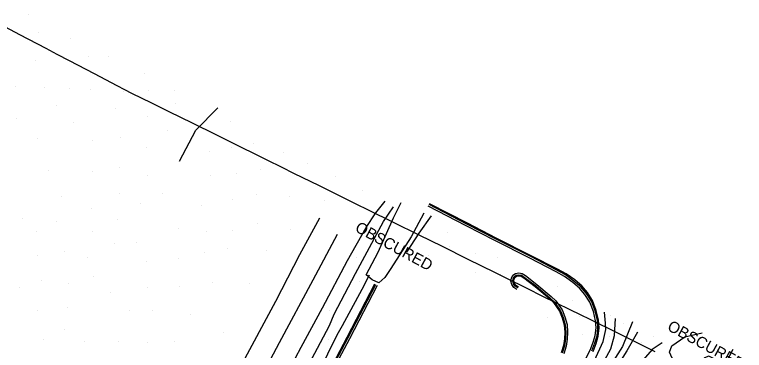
# Model space of a CAD drawing. Extents: x 1497074 to 1501343, y 481943 to 486114.
# Drawn here: x 1498306.3 to 1498696.9, y 483689.7 to 483869.7 of the extents above; entities that cross this region are included whole.
import ezdxf

# ---------------------------------------------------------------- set-up
doc = ezdxf.new("R2010")
doc.units = 0
for name, color, linetype in [('PH Exist DTM Boundary', 7, 'Continuous'), ('PH Exist DTM Breakline', 7, 'Continuous'), ('PH Exist DTM Obscure Area', 7, 'Continuous'), ('PH Exist DTM Obscure Area Text', 7, 'Continuous'), ('PH Exist DTM Point', 7, 'Continuous')]:
    doc.layers.add(name, color=color, linetype=linetype)

msp = doc.modelspace()

# ---------------------------------------------------------------- linework, layer by layer
at = {"layer": 'PH Exist DTM Boundary'}
msp.add_lwpolyline([(1498649.09, 483689.06), (1498644.16, 483691.49), (1498629.09, 483698.94), (1498614.35, 483706.23), (1498609.09, 483708.83), (1498603.71, 483711.49), (1498589.09, 483718.72), (1498580.54, 483722.94), (1498569.09, 483728.6), (1498563.25, 483731.49), (1498549.09, 483738.49), (1498535.25, 483745.34), (1498529.09, 483748.38), (1498522.79, 483751.49), (1498509.09, 483758.27), (1498495.69, 483764.89), (1498489.09, 483768.15), (1498482.34, 483771.49), (1498469.09, 483778.04), (1498456.14, 483784.44), (1498449.09, 483787.93), (1498441.88, 483791.49), (1498433.32, 483795.72), (1498429.09, 483797.81), (1498419.94, 483802.34), (1498409.09, 483807.7), (1498406.55, 483808.95), (1498401.42, 483811.49), (1498389.09, 483817.59), (1498379.79, 483822.19), (1498369.09, 483827.48), (1498365.25, 483829.38), (1498365.25, 483829.38), (1498361.22, 483831.49), (1498349.09, 483837.86), (1498335.68, 483844.9), (1498329.09, 483848.36), (1498323.13, 483851.49), (1498309.09, 483858.86), (1498293.57, 483867.02)], dxfattribs=at)
at = {"layer": 'PH Exist DTM Breakline'}
for points in [[(1498394.59, 483791.1), (1498403.33, 483807.83), (1498415.01, 483819.74)], [(1498447.55, 483668.63), (1498459.74, 483691.55), (1498471.13, 483712.57), (1498484.43, 483737.88), (1498494.44, 483755.53), (1498499.66, 483763.4), (1498504.61, 483769.78)], [(1498447.31, 483651.62), (1498456.12, 483667.84), (1498468.39, 483691), (1498474.9, 483703.04), (1498477.38, 483709.2), (1498488.75, 483730.88), (1498499.95, 483751.82), (1498503.73, 483758.77), (1498509.04, 483766.64)], [(1498609.26, 483680.32), (1498614.34, 483689.93), (1498615.96, 483694.09), (1498617.03, 483697.81), (1498617.51, 483701.92), (1498617.22, 483705.66), (1498616.12, 483710.64), (1498614.2, 483715.63), (1498611.52, 483719.72), (1498608.69, 483723.03), (1498605, 483726.12), (1498600.56, 483729.4), (1498596.06, 483731.92), (1498582.06, 483739.09), (1498563.27, 483748.6), (1498547.95, 483756.53), (1498527.67, 483767.02)], [(1498615.25, 483689.51), (1498616.91, 483693.77), (1498618.02, 483697.61), (1498618.52, 483701.9), (1498618.21, 483705.81), (1498617.08, 483710.93), (1498615.1, 483716.09), (1498612.32, 483720.32), (1498609.4, 483723.74), (1498605.62, 483726.91), (1498601.1, 483730.24), (1498596.54, 483732.8), (1498582.51, 483739.98), (1498563.73, 483749.49), (1498548.41, 483757.42), (1498528.13, 483767.91)], [(1498615.9, 483689.2), (1498617.58, 483693.5), (1498618.62, 483697.45), (1498619.13, 483701.83), (1498618.85, 483706.16), (1498617.62, 483711.19), (1498615.61, 483716.44), (1498612.96, 483720.71), (1498609.88, 483724.34), (1498606.08, 483727.58), (1498601.42, 483730.76), (1498596.77, 483733.24), (1498582.74, 483740.42), (1498563.96, 483749.93), (1498548.64, 483757.86), (1498528.36, 483768.35)], [(1498516.2, 483742.31), (1498522.77, 483752.51), (1498529.37, 483761.85)], [(1498469.5, 483760.69), (1498458.69, 483740.87), (1498445.85, 483715.88), (1498427.04, 483680.74), (1498412.85, 483653.78), (1498398.64, 483627.6), (1498382.78, 483598.45), (1498367.78, 483569.73), (1498363.44, 483561.65), (1498358.69, 483552.93), (1498349.41, 483535.78)], [(1498478.85, 483751.89), (1498465.83, 483727.47), (1498447.89, 483693.89), (1498430.39, 483660.8), (1498410.39, 483624.69), (1498396.32, 483598.79), (1498378.24, 483563.99), (1498373.07, 483554.34), (1498364.15, 483537.79)], [(1498462.83, 483653.45), (1498463.68, 483662.71), (1498467.39, 483674.3), (1498473.87, 483687.85), (1498477.52, 483695.25), (1498479.71, 483699.27), (1498481.74, 483703.02), (1498492.34, 483722.64), (1498496.18, 483730.2)], [(1498575.09, 483722.38), (1498573.54, 483723.47), (1498572.39, 483725.01), (1498571.87, 483726.78), (1498572.2, 483728.54), (1498572.98, 483729.98), (1498574.4, 483731), (1498576.13, 483731.28), (1498577.9, 483730.92), (1498579.67, 483729.8), (1498585.85, 483725.08), (1498593.5, 483718.71), (1498595.89, 483716.33), (1498599.3, 483711.51), (1498600.86, 483707.73), (1498601.99, 483703.69), (1498602.25, 483699.57), (1498602.05, 483695.78), (1498601.52, 483692.07), (1498600.31, 483687.96)], [(1498575.67, 483723.19), (1498574.25, 483724.2), (1498573.3, 483725.47), (1498572.9, 483726.83), (1498573.15, 483728.2), (1498573.75, 483729.3), (1498574.8, 483730.05), (1498576.11, 483730.27), (1498577.53, 483729.98), (1498579.1, 483728.98), (1498585.23, 483724.3), (1498592.83, 483717.97), (1498595.13, 483715.69), (1498598.42, 483711.02), (1498599.91, 483707.4), (1498600.99, 483703.52), (1498601.25, 483699.57), (1498601.05, 483695.88), (1498600.54, 483692.28), (1498599.37, 483688.31)], [(1498575.96, 483723.6), (1498574.6, 483724.56), (1498573.76, 483725.69), (1498573.41, 483726.86), (1498573.63, 483728.03), (1498574.13, 483728.96), (1498574.99, 483729.58), (1498576.1, 483729.76), (1498577.34, 483729.51), (1498578.81, 483728.57), (1498584.92, 483723.91), (1498592.49, 483717.6), (1498594.74, 483715.36), (1498597.98, 483710.78), (1498599.44, 483707.24), (1498600.5, 483703.43), (1498600.75, 483699.56), (1498600.55, 483695.93), (1498600.05, 483692.39), (1498598.9, 483688.48)], [(1498499, 483725.16), (1498484.14, 483696.71), (1498472.63, 483674.8), (1498469.77, 483668.91), (1498468.56, 483665.61), (1498468.16, 483661.61), (1498468.3, 483656.92), (1498469.19, 483651.15), (1498469.88, 483647.53), (1498470.59, 483644.55), (1498471.25, 483641.04), (1498471.75, 483638.62), (1498471.77, 483637.44), (1498471.41, 483636.54), (1498470.81, 483635.6), (1498470, 483634.96), (1498468.72, 483634.39), (1498458.46, 483630.94), (1498446.44, 483627.08), (1498434.98, 483604.76), (1498418.09, 483571.55), (1498405.83, 483547.74), (1498402.54, 483541.58)], [(1498499.44, 483724.93), (1498484.58, 483696.48), (1498473.08, 483674.58), (1498470.23, 483668.72), (1498469.05, 483665.5), (1498468.66, 483661.6), (1498468.8, 483656.96), (1498469.68, 483651.24), (1498470.37, 483647.64), (1498471.44, 483643.34), (1498471.87, 483640.8), (1498472.24, 483638.66), (1498472.27, 483637.35), (1498471.86, 483636.31), (1498471.19, 483635.26), (1498470.25, 483634.53), (1498468.9, 483633.93), (1498458.61, 483630.46), (1498446.79, 483626.67), (1498435.43, 483604.53), (1498418.53, 483571.32), (1498406.28, 483547.51), (1498402.99, 483541.34)], [(1498500.33, 483724.47), (1498485.47, 483696.01), (1498473.97, 483674.13), (1498471.15, 483668.33), (1498470.03, 483665.28), (1498469.66, 483661.56), (1498469.8, 483657.06), (1498470.67, 483651.41), (1498471.35, 483647.85), (1498472.42, 483643.55), (1498472.86, 483640.97), (1498473.24, 483638.76), (1498473.27, 483637.17), (1498472.76, 483635.85), (1498471.94, 483634.58), (1498470.77, 483633.67), (1498469.27, 483633), (1498458.93, 483629.51), (1498447.49, 483625.84), (1498436.32, 483604.08), (1498419.42, 483570.87), (1498407.16, 483547.04), (1498403.87, 483540.87)], [(1498607.62, 483660.62), (1498618.73, 483678.45), (1498625.37, 483690.67), (1498627.28, 483697.77), (1498627.89, 483706.87)], [(1498616.68, 483684.38), (1498621.23, 483694.54), (1498622.65, 483700.97), (1498622.59, 483704.26), (1498621.96, 483710.17)], [(1498637.05, 483704.99), (1498631.7, 483691.92), (1498619.12, 483672.24), (1498611, 483658.42), (1498607.04, 483651.85), (1498605.3, 483649.51)], [(1498639.72, 483699.61), (1498633.95, 483689.47), (1498626.48, 483677.64), (1498618.91, 483663.71), (1498612.15, 483651.28), (1498606.53, 483640.29)], [(1498652.87, 483693.82), (1498647.54, 483690.22), (1498642.72, 483684.67), (1498640.91, 483681.33), (1498632.44, 483665.76), (1498627.85, 483659.13), (1498625.92, 483656.1), (1498619.06, 483647.67), (1498617, 483644.56), (1498610.31, 483632.71), (1498602.41, 483618.88), (1498592.1, 483600.32), (1498583.97, 483584.33), (1498573.56, 483565.19), (1498565.32, 483546.58), (1498558.67, 483532.03), (1498554.72, 483524.73), (1498547.04, 483510.4), (1498540.16, 483495.31), (1498533.88, 483484.36), (1498530.79, 483479.09)]]:
    msp.add_lwpolyline(points, dxfattribs=at)
at = {"layer": 'PH Exist DTM Obscure Area'}
for points in [[(1498525.32, 483763.24), (1498518.48, 483750.67), (1498507.61, 483733.58), (1498504.39, 483728.88), (1498501.31, 483725.91), (1498497.66, 483727.52), (1498494.54, 483730.29), (1498500.85, 483742.33), (1498509.14, 483760.81), (1498513.11, 483768.91)], [(1498690.72, 483690.16), (1498686.86, 483683.07), (1498685.66, 483682.7), (1498677.93, 483686.67), (1498675.62, 483685.75), (1498672.91, 483680.83), (1498669.44, 483679.83), (1498662.45, 483682.75), (1498658.15, 483685.66), (1498656.82, 483688.74), (1498658.12, 483692.11), (1498665.06, 483697.03), (1498674.36, 483699.13)]]:
    msp.add_lwpolyline(points, dxfattribs=at)
at = {"layer": 'PH Exist DTM Point'}
for p, q in [((1498313.78, 483869.68), (1498313.78, 483869.68)), ((1498318.86, 483860.12), (1498318.86, 483860.12)), ((1498336.05, 483856.99), (1498336.05, 483856.99)), ((1498317.66, 483844.97), (1498317.66, 483844.97)), ((1498345.63, 483847.18), (1498345.63, 483847.18)), ((1498356.69, 483847), (1498356.69, 483847)), ((1498375.94, 483838.05), (1498375.94, 483838.05)), ((1498306.62, 483831.17), (1498306.62, 483831.17)), ((1498322.43, 483830.39), (1498322.43, 483830.39)), ((1498335.44, 483830.01), (1498335.44, 483830.01)), ((1498347.12, 483829.4), (1498347.12, 483829.4)), ((1498364.39, 483828.46), (1498364.39, 483828.46)), ((1498377.83, 483828.85), (1498377.83, 483828.85)), ((1498392.11, 483828.8), (1498392.11, 483828.8)), ((1498328.92, 483820.75), (1498328.92, 483820.75)), ((1498392.18, 483821.78), (1498392.18, 483821.78)), ((1498360.5, 483819.3), (1498360.5, 483819.3)), ((1498415.01, 483819.74), (1498415.01, 483819.74)), ((1498307.37, 483814.15), (1498307.37, 483814.15)), ((1498377.55, 483815.19), (1498377.55, 483815.19)), ((1498421.82, 483812.51), (1498421.82, 483812.51)), ((1498337.81, 483811.73), (1498337.81, 483811.73)), ((1498387.95, 483807.68), (1498387.95, 483807.68)), ((1498403.33, 483807.83), (1498403.33, 483807.83)), ((1498318.63, 483803.18), (1498318.63, 483803.18)), ((1498347.86, 483802.47), (1498347.86, 483802.47)), ((1498362.77, 483803.79), (1498362.77, 483803.79)), ((1498434.33, 483800.76), (1498434.33, 483800.76)), ((1498376.66, 483798.22), (1498376.66, 483798.22)), ((1498422.48, 483798.5), (1498422.48, 483798.5)), ((1498410.72, 483796.25), (1498410.72, 483796.25)), ((1498450.18, 483795.67), (1498450.18, 483795.67)), ((1498394.59, 483791.1), (1498394.59, 483791.1)), ((1498463.09, 483789.89), (1498463.09, 483789.89)), ((1498324.51, 483786.04), (1498324.51, 483786.04)), ((1498348.21, 483785.8), (1498348.21, 483785.8)), ((1498362.41, 483787.93), (1498362.41, 483787.93)), ((1498425.19, 483784.75), (1498425.19, 483784.75)), ((1498437.67, 483786.42), (1498437.67, 483786.42)), ((1498377.52, 483783.21), (1498377.52, 483783.21)), ((1498410.9, 483783.4), (1498410.9, 483783.4)), ((1498478.03, 483782.73), (1498478.03, 483782.73)), ((1498362.52, 483773.78), (1498362.52, 483773.78)), ((1498385.51, 483773.73), (1498385.51, 483773.73)), ((1498436.01, 483773.32), (1498436.01, 483773.32)), ((1498492.55, 483775.36), (1498492.55, 483775.36)), ((1498331.46, 483772.18), (1498331.46, 483772.18)), ((1498422.97, 483770.8), (1498422.97, 483770.8)), ((1498453.51, 483772.26), (1498453.51, 483772.26)), ((1498472.03, 483770.27), (1498472.03, 483770.27)), ((1498347.63, 483765.56), (1498347.63, 483765.56)), ((1498373.85, 483768.48), (1498373.85, 483768.48)), ((1498406.55, 483767.64), (1498406.55, 483767.64)), ((1498310.66, 483760.18), (1498310.66, 483760.18)), ((1498328.47, 483758.79), (1498328.47, 483758.79)), ((1498361.6, 483759.99), (1498361.6, 483759.99)), ((1498436.06, 483757.8), (1498436.06, 483757.8)), ((1498318.13, 483753.61), (1498318.13, 483753.61)), ((1498348.04, 483753.5), (1498348.04, 483753.5)), ((1498393.99, 483754.84), (1498393.99, 483754.84)), ((1498408.9, 483753.59), (1498408.9, 483753.59)), ((1498422.74, 483753.91), (1498422.74, 483753.91)), ((1498454.17, 483754.34), (1498454.17, 483754.34)), ((1498537.87, 483752.81), (1498537.87, 483752.81)), ((1498359.84, 483746.96), (1498359.84, 483746.96)), ((1498371.54, 483747.44), (1498371.54, 483747.44)), ((1498332.85, 483742.69), (1498332.85, 483742.69)), ((1498407.89, 483742.24), (1498407.89, 483742.24)), ((1498420.14, 483744.11), (1498420.14, 483744.11)), ((1498441.23, 483743.48), (1498441.23, 483743.48)), ((1498538.94, 483745.43), (1498538.94, 483745.43)), ((1498318.31, 483740.36), (1498318.31, 483740.36)), ((1498345.42, 483739.46), (1498345.42, 483739.46)), ((1498393.88, 483738.85), (1498393.88, 483738.85)), ((1498489.44, 483739.37), (1498489.44, 483739.37)), ((1498527.63, 483740.84), (1498527.63, 483740.84)), ((1498553.11, 483741.58), (1498553.11, 483741.58)), ((1498564.71, 483739.48), (1498564.71, 483739.48)), ((1498377.08, 483737.26), (1498377.08, 483737.26)), ((1498552.71, 483731.58), (1498552.71, 483731.58)), ((1498566.3, 483730.42), (1498566.3, 483730.42)), ((1498320.72, 483727.46), (1498320.72, 483727.46)), ((1498348.44, 483729.45), (1498348.44, 483729.45)), ((1498490.8, 483726.79), (1498490.8, 483726.79)), ((1498308.96, 483723.46), (1498308.96, 483723.46)), ((1498334.96, 483725.6), (1498334.96, 483725.6)), ((1498377.4, 483723.33), (1498377.4, 483723.33)), ((1498394.34, 483723.99), (1498394.34, 483723.99)), ((1498412.38, 483726.1), (1498412.38, 483726.1)), ((1498432.27, 483725.61), (1498432.27, 483725.61)), ((1498597.12, 483724.03), (1498597.12, 483724.03)), ((1498357.79, 483720.88), (1498357.79, 483720.88)), ((1498604.75, 483716.49), (1498604.75, 483716.49)), ((1498318.65, 483710.96), (1498318.65, 483710.96)), ((1498334.39, 483712.83), (1498334.39, 483712.83)), ((1498367.8, 483711.03), (1498367.8, 483711.03)), ((1498380.27, 483711.31), (1498380.27, 483711.31)), ((1498474.72, 483711.22), (1498474.72, 483711.22)), ((1498400.56, 483708.99), (1498400.56, 483708.99)), ((1498591.72, 483707.23), (1498591.72, 483707.23)), ((1498608.69, 483707.94), (1498608.69, 483707.94)), ((1498625.21, 483708.59), (1498625.21, 483708.59)), ((1498632.07, 483704.13), (1498632.07, 483704.13)), ((1498333.22, 483700.73), (1498333.22, 483700.73)), ((1498418.08, 483699.49), (1498418.08, 483699.49)), ((1498321.73, 483695.36), (1498321.73, 483695.36)), ((1498474.47, 483695.53), (1498474.47, 483695.53)), ((1498610, 483698.22), (1498610, 483698.22)), ((1498624.6, 483696.97), (1498624.6, 483696.97)), ((1498648, 483696.99), (1498648, 483696.99)), ((1498343.92, 483694.62), (1498343.92, 483694.62)), ((1498362.03, 483694.54), (1498362.03, 483694.54)), ((1498377.46, 483694.04), (1498377.46, 483694.04)), ((1498391.77, 483694.55), (1498391.77, 483694.55)), ((1498641.81, 483693.74), (1498641.81, 483693.74))]:
    msp.add_line(p, q, dxfattribs=at)

# ---------------------------------------------------------------- texts
at = {"layer": 'PH Exist DTM Obscure Area Text'}
for p in [(1498488.03, 483753.85), (1498655.14, 483700.91)]:
    msp.add_text('OBSCURED', height=6, rotation=331.4703, dxfattribs=at).set_placement(p)

doc.saveas('drawing.dxf')
